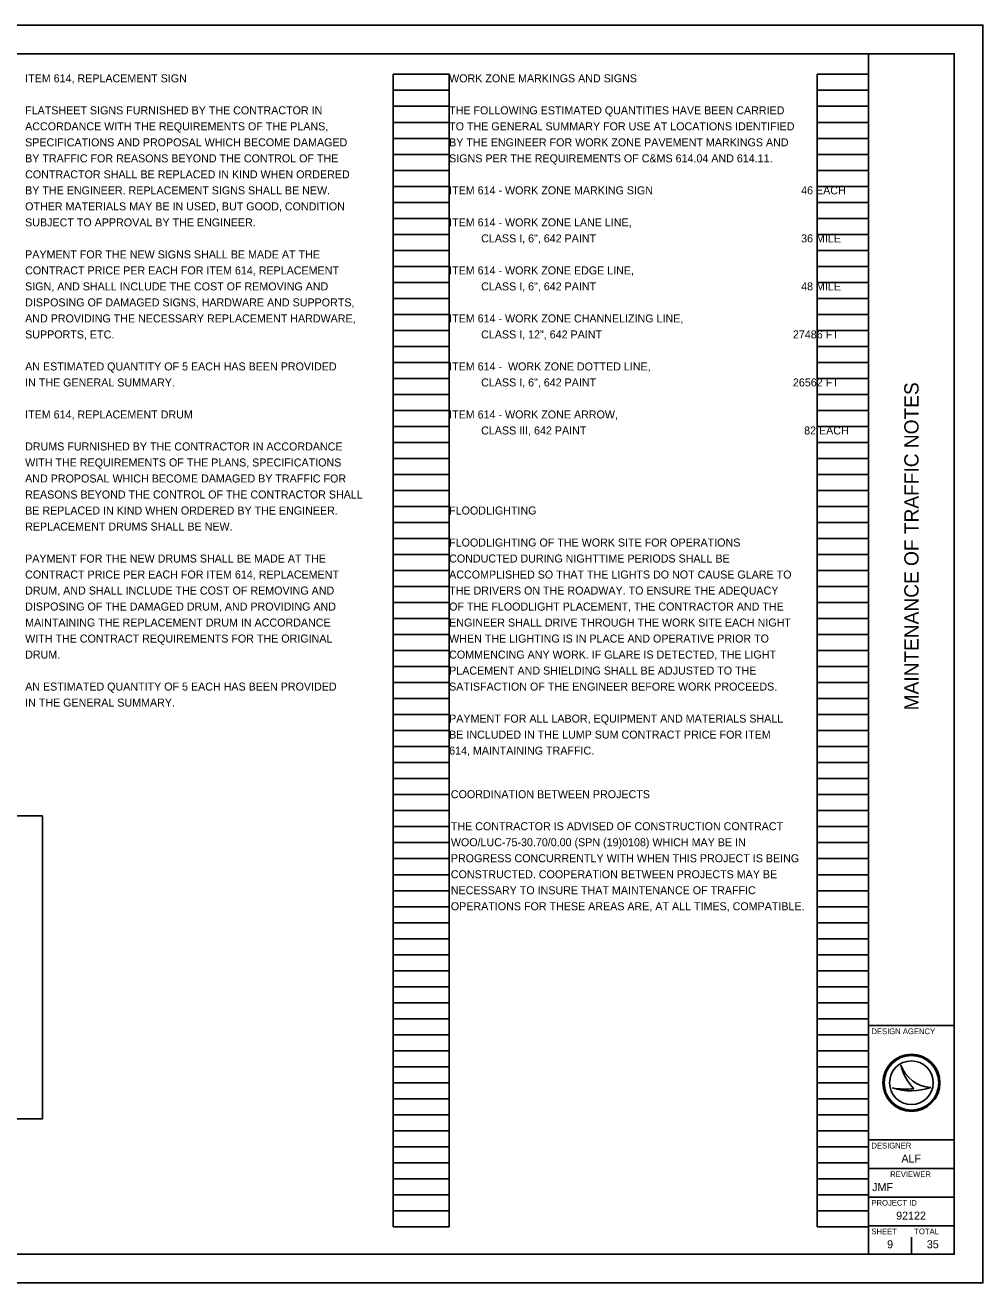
# Model space of a CAD drawing. Extents: x 0 to 34, y 0 to 22.
# Drawn here: x 17.24 to 34, y 0 to 22 of the extents above; entities that cross this region are included whole.
import ezdxf

# ---------------------------------------------------------------- set-up
doc = ezdxf.new("R2010")
doc.units = 0
for name, color, linetype in [('Default', 7, 'Continuous'), ('SH_Border', 7, 'Continuous'), ('SH_Cut_Line', 7, 'Continuous'), ('SH_Data', 7, 'Continuous'), ('SH_Text', 7, 'Continuous')]:
    doc.layers.add(name, color=color, linetype=linetype)

msp = doc.modelspace()

# ---------------------------------------------------------------- linework, layer by layer
at = {"layer": 'Default'}
msp.add_lwpolyline([(9.49, 2.867), (17.542, 2.867), (17.542, 8.168), (9.49, 8.168)], close=True, dxfattribs=at)
at = {"layer": 'SH_Border'}
for p, q in [((32, 0.5), (32, 21.5)), ((32, 4.5), (33.5, 4.5)), ((32, 2.5), (33.5, 2.5)), ((32, 2), (33.5, 2)), ((32, 1.5), (33.5, 1.5)), ((32, 1), (33.5, 1))]:
    msp.add_line(p, q, dxfattribs=at)
msp.add_lwpolyline([(1.5, 21.5), (33.5, 21.5), (33.5, 0.5), (1.5, 0.5)], close=True, dxfattribs=at)
at = {"layer": 'SH_Cut_Line'}
msp.add_lwpolyline([(0, 0), (34, 0), (34, 22), (0, 22)], close=True, dxfattribs=at)
at = {"layer": 'SH_Data'}
for p, q in [((23.68, 0.98), (23.68, 21.14)), ((23.68, 21.14), (24.66, 21.14)), ((24.66, 0.98), (24.66, 21.14)), ((31.1, 0.98), (31.1, 21.14)), ((31.1, 21.14), (32, 21.14)), ((32, 0.98), (32, 21.14)), ((23.68, 20.86), (24.66, 20.86)), ((31.1, 20.86), (32, 20.86)), ((23.68, 20.58), (24.66, 20.58)), ((31.1, 20.58), (32, 20.58)), ((23.68, 20.3), (24.66, 20.3)), ((31.1, 20.3), (32, 20.3)), ((23.68, 20.02), (24.66, 20.02)), ((31.1, 20.02), (32, 20.02)), ((23.68, 19.74), (24.66, 19.74)), ((31.1, 19.74), (32, 19.74)), ((23.68, 19.46), (24.66, 19.46)), ((31.1, 19.46), (32, 19.46)), ((23.68, 19.18), (24.66, 19.18)), ((31.1, 19.18), (32, 19.18)), ((23.68, 18.9), (24.66, 18.9)), ((31.1, 18.9), (32, 18.9)), ((23.68, 18.62), (24.66, 18.62)), ((31.1, 18.62), (32, 18.62)), ((23.68, 18.34), (24.66, 18.34)), ((31.1, 18.34), (32, 18.34)), ((23.68, 18.06), (24.66, 18.06)), ((31.1, 18.06), (32, 18.06)), ((23.68, 17.78), (24.66, 17.78)), ((31.1, 17.78), (32, 17.78)), ((23.68, 17.5), (24.66, 17.5)), ((31.1, 17.5), (32, 17.5)), ((23.68, 17.22), (24.66, 17.22)), ((31.1, 17.22), (32, 17.22)), ((23.68, 16.94), (24.66, 16.94)), ((31.1, 16.94), (32, 16.94)), ((23.68, 16.66), (24.66, 16.66)), ((31.1, 16.66), (32, 16.66)), ((23.68, 16.38), (24.66, 16.38)), ((31.1, 16.38), (32, 16.38)), ((23.68, 16.1), (24.66, 16.1)), ((31.1, 16.1), (32, 16.1)), ((23.68, 15.82), (24.66, 15.82)), ((31.1, 15.82), (32, 15.82)), ((23.68, 15.54), (24.66, 15.54)), ((31.1, 15.54), (32, 15.54)), ((23.68, 15.26), (24.66, 15.26)), ((31.1, 15.26), (32, 15.26)), ((23.68, 14.98), (24.66, 14.98)), ((31.1, 14.98), (32, 14.98)), ((23.68, 14.7), (24.66, 14.7)), ((31.1, 14.7), (32, 14.7)), ((23.68, 14.42), (24.66, 14.42)), ((31.1, 14.42), (32, 14.42)), ((23.68, 14.14), (24.66, 14.14)), ((31.1, 14.14), (32, 14.14)), ((23.68, 13.86), (24.66, 13.86)), ((31.1, 13.86), (32, 13.86)), ((23.68, 13.58), (24.66, 13.58)), ((31.1, 13.58), (32, 13.58)), ((23.68, 13.3), (24.66, 13.3)), ((31.1, 13.3), (32, 13.3)), ((23.68, 13.02), (24.66, 13.02)), ((31.1, 13.02), (32, 13.02)), ((23.68, 12.74), (24.66, 12.74)), ((31.1, 12.74), (32, 12.74)), ((23.68, 12.46), (24.66, 12.46)), ((31.1, 12.46), (32, 12.46)), ((23.68, 12.18), (24.66, 12.18)), ((31.1, 12.18), (32, 12.18)), ((23.68, 11.9), (24.66, 11.9)), ((31.1, 11.9), (32, 11.9)), ((23.68, 11.62), (24.66, 11.62)), ((31.1, 11.62), (32, 11.62)), ((23.68, 11.34), (24.66, 11.34)), ((31.1, 11.34), (32, 11.34)), ((23.68, 11.06), (24.66, 11.06)), ((31.1, 11.06), (32, 11.06)), ((23.68, 10.78), (24.66, 10.78)), ((31.1, 10.78), (32, 10.78)), ((23.68, 10.5), (24.66, 10.5)), ((31.1, 10.5), (32, 10.5)), ((23.68, 10.22), (24.66, 10.22)), ((31.1, 10.22), (32, 10.22)), ((23.68, 9.94), (24.66, 9.94)), ((31.1, 9.94), (32, 9.94)), ((23.68, 9.66), (24.66, 9.66)), ((31.1, 9.66), (32, 9.66)), ((23.68, 9.38), (24.66, 9.38)), ((31.1, 9.38), (32, 9.38)), ((23.68, 9.1), (24.66, 9.1)), ((31.1, 9.1), (32, 9.1)), ((23.68, 8.82), (24.66, 8.82)), ((31.1, 8.82), (32, 8.82)), ((23.68, 8.54), (24.66, 8.54)), ((31.1, 8.54), (32, 8.54)), ((23.68, 8.26), (24.66, 8.26)), ((31.1, 8.26), (32, 8.26)), ((23.68, 7.98), (24.66, 7.98)), ((31.1, 7.98), (32, 7.98)), ((23.68, 7.7), (24.66, 7.7)), ((31.1, 7.7), (32, 7.7)), ((23.68, 7.42), (24.66, 7.42)), ((31.1, 7.42), (32, 7.42)), ((23.68, 7.14), (24.66, 7.14)), ((31.1, 7.14), (32, 7.14)), ((23.68, 6.86), (24.66, 6.86)), ((31.1, 6.86), (32, 6.86)), ((23.68, 6.58), (24.66, 6.58)), ((31.1, 6.58), (32, 6.58)), ((23.68, 6.3), (24.66, 6.3)), ((31.1, 6.3), (32, 6.3)), ((23.68, 6.02), (24.66, 6.02)), ((31.1, 6.02), (32, 6.02)), ((23.68, 5.74), (24.66, 5.74)), ((31.1, 5.74), (32, 5.74)), ((23.68, 5.46), (24.66, 5.46)), ((31.1, 5.46), (32, 5.46)), ((23.68, 5.18), (24.66, 5.18)), ((31.1, 5.18), (32, 5.18)), ((23.68, 4.9), (24.66, 4.9)), ((31.1, 4.9), (32, 4.9)), ((23.68, 4.62), (24.66, 4.62)), ((31.1, 4.62), (32, 4.62)), ((23.68, 4.34), (24.66, 4.34)), ((31.1, 4.34), (32, 4.34)), ((23.68, 4.06), (24.66, 4.06)), ((31.1, 4.06), (32, 4.06)), ((23.68, 3.78), (24.66, 3.78)), ((31.1, 3.78), (32, 3.78)), ((32.567, 3.81), (32.567, 3.81)), ((23.68, 3.5), (24.66, 3.5)), ((31.1, 3.5), (32, 3.5)), ((32.417, 3.41), (32.417, 3.41)), ((32.75, 3.5), (32.75, 3.5)), ((33.087, 3.419), (33.087, 3.419)), ((23.68, 3.22), (24.66, 3.22)), ((31.1, 3.22), (32, 3.22)), ((23.68, 2.94), (24.66, 2.94)), ((31.1, 2.94), (32, 2.94)), ((23.68, 2.66), (24.66, 2.66)), ((31.1, 2.66), (32, 2.66)), ((23.68, 2.38), (24.66, 2.38)), ((31.1, 2.38), (32, 2.38)), ((23.68, 2.1), (24.66, 2.1)), ((31.1, 2.1), (32, 2.1)), ((23.68, 1.82), (24.66, 1.82)), ((31.1, 1.82), (32, 1.82)), ((23.68, 1.54), (24.66, 1.54)), ((31.1, 1.54), (32, 1.54)), ((23.68, 1.26), (24.66, 1.26)), ((31.1, 1.26), (32, 1.26)), ((23.68, 0.98), (24.66, 0.98)), ((31.1, 0.98), (32, 0.98)), ((32.375, 0.675), (32.375, 0.675)), ((32.75, 0.5), (32.75, 0.8))]:
    msp.add_line(p, q, dxfattribs=at)
for radius in [0.5, 0.477, 0.477, 0.382]:
    msp.add_circle((32.75, 3.5), radius, dxfattribs=at)
for centre, radius, start, end in [((33.116, 3.998), 0.58, 198.9257, 198.9319), ((33.347, 3.97), 0.796, 191.6379, 191.6421), ((33.116, 3.998), 0.58, 198.9319, 267.1657), ((33.347, 3.97), 0.796, 191.6421, 226.0947), ((32.739, 4.37), 1.013, 251.4576, 290.0832), ((32.648, 4.654), 1.266, 259.4964, 259.4995), ((32.739, 4.37), 1.013, 251.4527, 251.4576), ((32.648, 4.654), 1.266, 259.4995, 276.6672)]:
    msp.add_arc(centre, radius, start, end, dxfattribs=at)

# ---------------------------------------------------------------- texts
msp.add_text('MAINTENANCE OF TRAFFIC NOTES', height=0.25, rotation=90, dxfattribs=at).set_placement((32.875, 10.014))
for s, height, p in [('DESIGN AGENCY', 0.1, (32.05, 4.35)), ('DESIGNER', 0.1, (32.05, 2.35)), ('ALF', 0.14, (32.575, 2.105)), ('REVIEWER', 0.1, (32.378, 1.85)), ('JMF', 0.14, (32.064, 1.605)), ('PROJECT ID', 0.1, (32.05, 1.35)), ('92122', 0.14, (32.483, 1.105)), ('SHEET', 0.1, (32.05, 0.85)), ('TOTAL', 0.1, (32.8, 0.85)), ('9', 0.14, (32.325, 0.605)), ('35', 0.14, (33.02, 0.605))]:
    msp.add_text(s, height=height, dxfattribs=at).set_placement(p)
at = {"layer": 'SH_Text'}
for s, p in [('ITEM 614, REPLACEMENT SIGN', (17.24, 21)), ('WORK ZONE MARKINGS AND SIGNS', (24.66, 21)), ('FLATSHEET SIGNS FURNISHED BY THE CONTRACTOR IN', (17.24, 20.44)), ('THE FOLLOWING ESTIMATED QUANTITIES HAVE BEEN CARRIED', (24.66, 20.44)), ('ACCORDANCE WITH THE REQUIREMENTS OF THE PLANS,', (17.24, 20.16)), ('TO THE GENERAL SUMMARY FOR USE AT LOCATIONS IDENTIFIED', (24.66, 20.16)), ('SPECIFICATIONS AND PROPOSAL WHICH BECOME DAMAGED', (17.24, 19.88)), ('BY THE ENGINEER FOR WORK ZONE PAVEMENT MARKINGS AND', (24.66, 19.88)), ('BY TRAFFIC FOR REASONS BEYOND THE CONTROL OF THE', (17.24, 19.6)), ('SIGNS PER THE REQUIREMENTS OF C&MS 614.04 AND 614.11.', (24.66, 19.6)), ('CONTRACTOR SHALL BE REPLACED IN KIND WHEN ORDERED', (17.24, 19.32)), ('BY THE ENGINEER. REPLACEMENT SIGNS SHALL BE NEW.', (17.24, 19.04)), ('ITEM 614 - WORK ZONE MARKING SIGN', (24.66, 19.04)), ('46 EACH', (30.82, 19.04)), ('OTHER MATERIALS MAY BE IN USED, BUT GOOD, CONDITION', (17.24, 18.76)), ('SUBJECT TO APPROVAL BY THE ENGINEER.', (17.24, 18.48)), ('ITEM 614 - WORK ZONE LANE LINE,', (24.66, 18.48)), ('CLASS I, 6", 642 PAINT', (25.22, 18.2)), ('36 MILE', (30.82, 18.2)), ('PAYMENT FOR THE NEW SIGNS SHALL BE MADE AT THE', (17.24, 17.92)), ('CONTRACT PRICE PER EACH FOR ITEM 614, REPLACEMENT', (17.24, 17.64)), ('ITEM 614 - WORK ZONE EDGE LINE,', (24.66, 17.64)), ('SIGN, AND SHALL INCLUDE THE COST OF REMOVING AND', (17.24, 17.36)), ('CLASS I, 6", 642 PAINT', (25.22, 17.36)), ('48 MILE', (30.82, 17.36)), ('DISPOSING OF DAMAGED SIGNS, HARDWARE AND SUPPORTS,', (17.24, 17.08)), ('AND PROVIDING THE NECESSARY REPLACEMENT HARDWARE,', (17.24, 16.8)), ('ITEM 614 - WORK ZONE CHANNELIZING LINE,', (24.66, 16.8)), ('SUPPORTS, ETC.', (17.24, 16.52)), ('CLASS I, 12", 642 PAINT', (25.22, 16.52)), ('        27486 FT', (30.26, 16.52)), ('AN ESTIMATED QUANTITY OF 5 EACH HAS BEEN PROVIDED', (17.24, 15.96)), ('ITEM 614 -  WORK ZONE DOTTED LINE,', (24.66, 15.96)), ('IN THE GENERAL SUMMARY.', (17.24, 15.68)), ('CLASS I, 6", 642 PAINT', (25.22, 15.68)), ('        26562 FT', (30.26, 15.68)), ('ITEM 614, REPLACEMENT DRUM', (17.24, 15.12)), ('ITEM 614 - WORK ZONE ARROW,', (24.66, 15.12)), ('CLASS III, 642 PAINT', (25.22, 14.84)), (' 82 EACH', (30.82, 14.84)), ('DRUMS FURNISHED BY THE CONTRACTOR IN ACCORDANCE', (17.24, 14.56)), ('WITH THE REQUIREMENTS OF THE PLANS, SPECIFICATIONS', (17.24, 14.28)), ('AND PROPOSAL WHICH BECOME DAMAGED BY TRAFFIC FOR', (17.24, 14)), ('REASONS BEYOND THE CONTROL OF THE CONTRACTOR SHALL', (17.24, 13.72)), ('BE REPLACED IN KIND WHEN ORDERED BY THE ENGINEER.', (17.24, 13.44)), ('FLOODLIGHTING', (24.66, 13.44)), ('REPLACEMENT DRUMS SHALL BE NEW.', (17.24, 13.16)), ('FLOODLIGHTING OF THE WORK SITE FOR OPERATIONS', (24.66, 12.88)), ('PAYMENT FOR THE NEW DRUMS SHALL BE MADE AT THE', (17.24, 12.6)), ('CONDUCTED DURING NIGHTTIME PERIODS SHALL BE', (24.66, 12.6)), ('CONTRACT PRICE PER EACH FOR ITEM 614, REPLACEMENT', (17.24, 12.32)), ('ACCOMPLISHED SO THAT THE LIGHTS DO NOT CAUSE GLARE TO', (24.66, 12.32)), ('DRUM, AND SHALL INCLUDE THE COST OF REMOVING AND', (17.24, 12.04)), ('THE DRIVERS ON THE ROADWAY. TO ENSURE THE ADEQUACY', (24.66, 12.04)), ('DISPOSING OF THE DAMAGED DRUM, AND PROVIDING AND', (17.24, 11.76)), ('OF THE FLOODLIGHT PLACEMENT, THE CONTRACTOR AND THE', (24.66, 11.76)), ('MAINTAINING THE REPLACEMENT DRUM IN ACCORDANCE', (17.24, 11.48)), ('ENGINEER SHALL DRIVE THROUGH THE WORK SITE EACH NIGHT', (24.66, 11.48)), ('WITH THE CONTRACT REQUIREMENTS FOR THE ORIGINAL', (17.24, 11.2)), ('WHEN THE LIGHTING IS IN PLACE AND OPERATIVE PRIOR TO', (24.66, 11.2)), ('DRUM.', (17.24, 10.92)), ('COMMENCING ANY WORK. IF GLARE IS DETECTED, THE LIGHT', (24.66, 10.92)), ('PLACEMENT AND SHIELDING SHALL BE ADJUSTED TO THE', (24.66, 10.64)), ('AN ESTIMATED QUANTITY OF 5 EACH HAS BEEN PROVIDED', (17.24, 10.36)), ('SATISFACTION OF THE ENGINEER BEFORE WORK PROCEEDS.', (24.66, 10.36)), ('IN THE GENERAL SUMMARY.', (17.24, 10.08)), ('PAYMENT FOR ALL LABOR, EQUIPMENT AND MATERIALS SHALL', (24.66, 9.8)), ('BE INCLUDED IN THE LUMP SUM CONTRACT PRICE FOR ITEM', (24.66, 9.52)), ('614, MAINTAINING TRAFFIC.', (24.66, 9.24)), ('COORDINATION BETWEEN PROJECTS', (24.69, 8.477)), ('THE CONTRACTOR IS ADVISED OF CONSTRUCTION CONTRACT', (24.69, 7.917)), ('WOO/LUC-75-30.70/0.00 (SPN (19)0108) WHICH MAY BE IN', (24.69, 7.637)), ('PROGRESS CONCURRENTLY WITH WHEN THIS PROJECT IS BEING', (24.69, 7.357)), ('CONSTRUCTED. COOPERATION BETWEEN PROJECTS MAY BE', (24.69, 7.077)), ('NECESSARY TO INSURE THAT MAINTENANCE OF TRAFFIC', (24.69, 6.797)), ('OPERATIONS FOR THESE AREAS ARE, AT ALL TIMES, COMPATIBLE.', (24.69, 6.517))]:
    msp.add_text(s, height=0.14, dxfattribs=at).set_placement(p)

doc.saveas('drawing.dxf')
